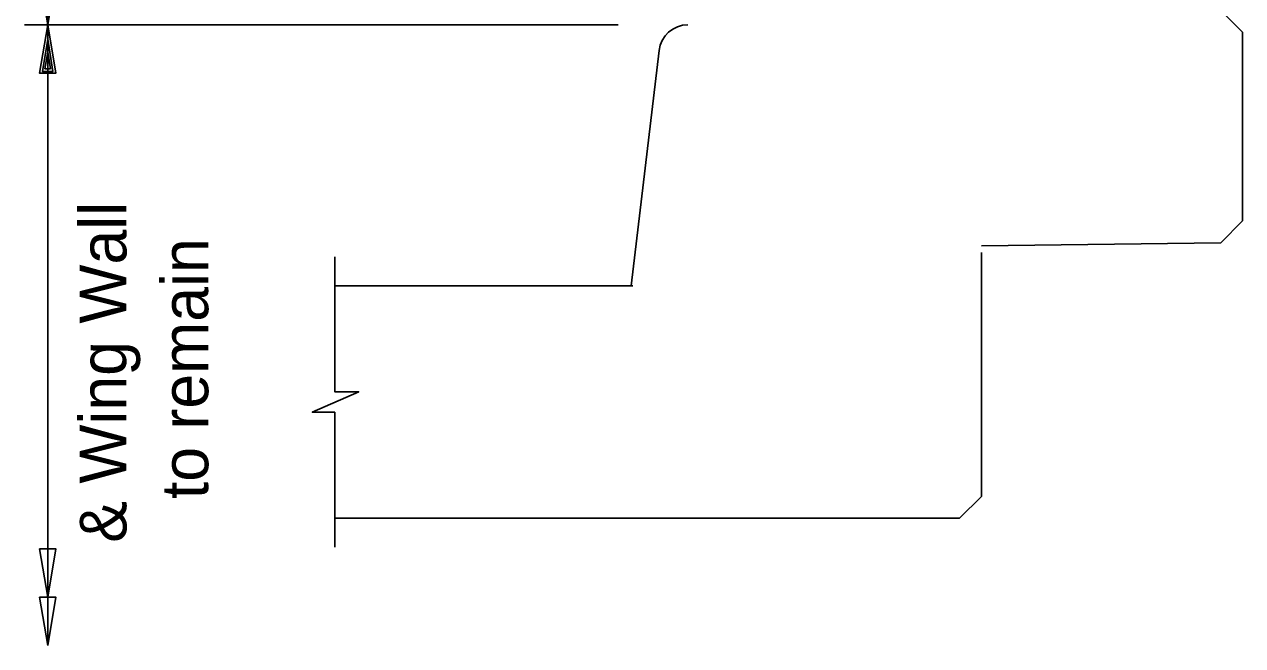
# Model space of a CAD drawing. Extents: x 0 to 41.1, y 0 to 25.9.
# Drawn here: x 19.92 to 25.17, y 6.38 to 9.06 of the extents above; entities that cross this region are included whole.
import ezdxf

# ---------------------------------------------------------------- set-up
doc = ezdxf.new("R2010")
doc.units = 0
doc.layers.add('Dimension', color=7, linetype='Continuous')
doc.layers.add('TrafBarrierConc', color=7, linetype='Continuous')

# ---------------------------------------------------------------- blocks, each defined once
blk = doc.blocks.new('ALT')
at = {"layer": 'Dimension'}
for points in [[(0, 0), (-0.00041, -0.000069), (-0.00041, 0.000069)], [(-0.000121, 0), (-0.000397, -0.000043), (-0.000397, 0.000043)], [(-0.000233, 0), (-0.000374, -0.000023), (-0.000374, 0.000023)]]:
    blk.add_lwpolyline(points, close=True, dxfattribs=at)

msp = doc.modelspace()

# ---------------------------------------------------------------- linework, layer by layer
at = {"layer": 'Dimension'}
for p, q in [((20.0247, 12.4283), (20.0247, 6.379)), ((22.4812, 9.0533), (19.9239, 9.0533))]:
    msp.add_line(p, q, dxfattribs=at)
msp.add_lwpolyline([(21.2601, 8.0533), (21.2601, 7.4725), (21.3635, 7.4725), (21.1635, 7.3841), (21.2601, 7.3841), (21.2601, 6.8033)], dxfattribs=at)
for points in [[(20.0246, 6.5872), (20.0598, 6.7955), (19.9893, 6.7955)], [(20.0246, 6.379), (20.0598, 6.5872), (19.9893, 6.5872)]]:
    msp.add_lwpolyline(points, close=True, dxfattribs=at)
at = {"layer": 'TrafBarrierConc'}
for p, q in [((25.1692, 9.0208), (25.0754, 9.1145)), ((25.1692, 8.2083), (25.1692, 9.0208)), ((22.6569, 8.9421), (22.536, 7.9283)), ((25.1692, 8.2083), (25.0754, 8.1145)), ((24.0442, 8.1004), (25.0754, 8.1145)), ((24.0442, 7.022), (24.0442, 8.0722)), ((21.2601, 7.9283), (22.5442, 7.9283)), ((24.0442, 7.022), (23.9505, 6.9283)), ((21.2601, 6.9283), (23.9505, 6.9283))]:
    msp.add_line(p, q, dxfattribs=at)
msp.add_arc((22.7811, 8.9283), 0.125, 90, 173.6598, dxfattribs=at)

# ---------------------------------------------------------------- block references
at = {"layer": 'Dimension', "xscale": 506.22200000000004}
for p, yscale, rotation in [((20.0243, 9.0529), 511.7797619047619, -90), ((20.0243, 9.0528), -511.7797619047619, 90)]:
    msp.add_blockref('ALT', p, dxfattribs=dict(at, yscale=yscale, rotation=rotation))

# ---------------------------------------------------------------- texts
at = {"layer": 'Dimension'}
for s, p in [('& Wing Wall', (20.3636, 6.8222)), ('to remain', (20.7156, 7.0102))]:
    msp.add_text(s, height=0.2016, rotation=90, dxfattribs=at).set_placement(p)

doc.saveas('drawing.dxf')
